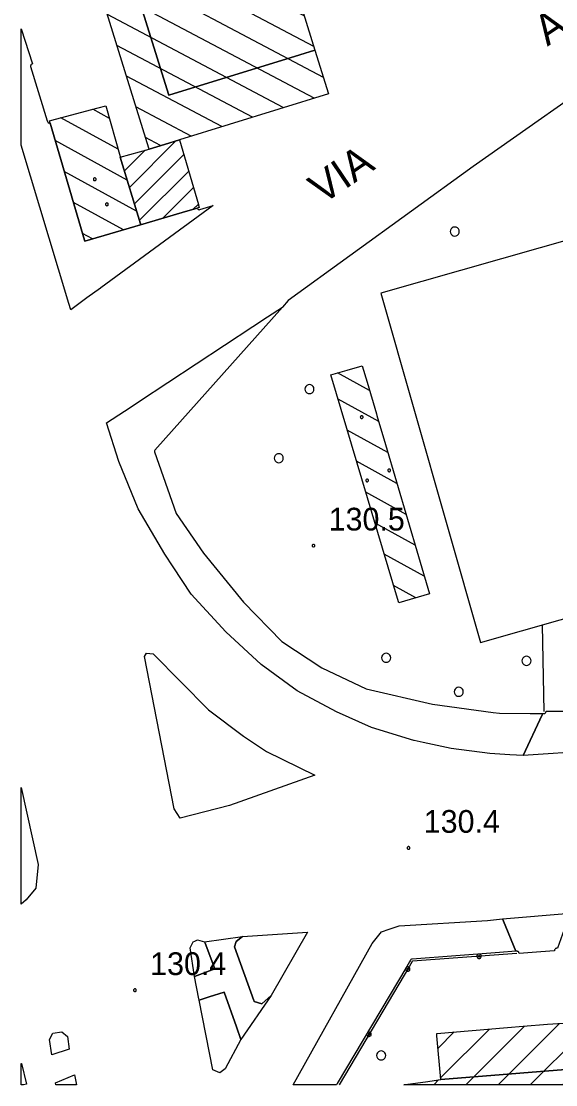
# Model space of a CAD drawing. Extents: x 513373 to 514978, y 5038576 to 5040180.
# Drawn here: x 513373 to 513408.3, y 5038580.1 to 5038650.3 of the extents above; entities that cross this region are included whole.
import ezdxf

# ---------------------------------------------------------------- set-up
doc = ezdxf.new("R2010")
doc.units = 0
for name, color, linetype in [('2010300', 7, 'Continuous'), ('3010204', 7, 'Continuous'), ('3060104', 7, 'Continuous'), ('B1211', 7, 'Continuous'), ('C1131', 7, 'Continuous'), ('C12211', 7, 'Continuous'), ('C21111', 7, 'Continuous'), ('C21152', 7, 'Continuous'), ('C2911', 7, 'Continuous'), ('CAMP_C12211', 7, 'Continuous'), ('CAMP_C21111', 7, 'Continuous'), ('Default', 7, 'Continuous'), ('F12107', 7, 'Continuous'), ('F12131', 7, 'Continuous'), ('F12132', 7, 'Continuous'), ('G4315', 7, 'Continuous'), ('TOP500', 7, 'Continuous'), ('TOP920', 7, 'Continuous')]:
    doc.layers.add(name, color=color, linetype=linetype)

# ---------------------------------------------------------------- blocks, each defined once
blk = doc.blocks.new('CAMP_1CE415D7')
at = {"layer": 'CAMP_C12211'}
for p, q in [((2.937, -2.063), (7.928, 2.928)), ((5.058, -2.063), (10.238, 3.116)), ((7.18, -2.063), (12.549, 3.306)), ((-5.548, -2.063), (-1.311, 2.174)), ((-3.427, -2.063), (0.999, 2.362)), ((-1.306, -2.063), (3.309, 2.551)), ((0.816, -2.063), (5.618, 2.739)), ((-11.619, 0.351), (-10.551, 1.42)), ((-11.442, -1.593), (-8.241, 1.608)), ((-9.791, -2.063), (-5.931, 1.797)), ((-7.669, -2.063), (-3.621, 1.986)), ((9.301, -2.063), (13.227, 1.863)), ((11.422, -2.063), (13.385, -0.1)), ((-11.912, -2.063), (-11.599, -1.75))]:
    blk.add_line(p, q, dxfattribs=at)
blk = doc.blocks.new('CAMP_4260F104')
at = {"layer": 'CAMP_C12211'}
for p, q in [((-0.738, 6.397), (-2.86, 7.563)), ((-0.137, 4.354), (-2.818, 5.829)), ((0.464, 2.312), (-2.208, 3.781)), ((1.065, 0.27), (-1.598, 1.734)), ((1.666, -1.772), (-0.988, -0.313)), ((2.267, -3.814), (-0.378, -2.36)), ((2.868, -5.856), (0.232, -4.407)), ((2.32, -7.267), (0.842, -6.454))]:
    blk.add_line(p, q, dxfattribs=at)
blk = doc.blocks.new('CAMP_4F2082C4')
at = {"layer": 'CAMP_C12211'}
for p, q in [((0.976, 3.743), (-0.129, 4.35)), ((1.54, 1.721), (-2.225, 3.791)), ((2.143, -0.322), (-2.606, 2.288)), ((2.759, -2.373), (-2.004, 0.246)), ((1.887, -3.605), (-1.402, -1.797)), ((-0.139, -4.203), (-0.8, -3.839))]:
    blk.add_line(p, q, dxfattribs=at)
blk = doc.blocks.new('CAMP_3A5802B0')
at = {"layer": 'CAMP_C12211'}
for p, q in [((-2.527, 26.797), (-4.04, 27.598)), ((-1.899, 24.767), (-6.054, 26.968)), ((-1.271, 22.738), (-7.369, 25.967)), ((-0.644, 20.708), (-7.369, 24.269)), ((-0.016, 18.679), (-7.369, 22.572)), ((0.612, 16.649), (-7.369, 20.875)), ((1.24, 14.619), (-7.369, 19.177)), ((1.867, 12.59), (-7.369, 17.48)), ((2.495, 10.56), (-7.369, 15.783)), ((3.123, 8.53), (-7.369, 14.086)), ((3.75, 6.501), (-7.369, 12.388)), ((4.378, 4.471), (-7.369, 10.691)), ((5.006, 2.441), (-7.369, 8.994)), ((5.634, 0.412), (-7.37, 7.297)), ((6.261, -1.618), (-7.37, 5.599)), ((6.889, -3.648), (-7.37, 3.902)), ((7.517, -5.677), (-7.37, 2.205)), ((8.144, -7.707), (-7.345, 0.494)), ((8.772, -9.736), (-6.717, -1.535)), ((9.4, -11.766), (-6.089, -3.565)), ((10.028, -13.796), (-5.461, -5.595)), ((10.655, -15.825), (-4.833, -7.625)), ((11.283, -17.855), (-4.206, -9.654)), ((11.911, -19.885), (-3.578, -11.684)), ((12.539, -21.914), (-2.95, -13.714)), ((11.923, -23.286), (-2.322, -15.743)), ((9.9, -23.912), (-1.695, -17.773)), ((7.876, -24.538), (-1.067, -19.803)), ((5.853, -25.164), (-0.439, -21.832)), ((3.829, -25.79), (0.188, -23.862)), ((1.806, -26.415), (0.816, -25.891))]:
    blk.add_line(p, q, dxfattribs=at)
blk = doc.blocks.new('CAMP_029225B5')
at = {"layer": 'CAMP_C21111'}
for p, q in [((-2.285, -0.164), (0.782, 2.904)), ((-2.612, 0.924), (-1.253, 2.283)), ((-1.959, -1.251), (1.301, 2.008)), ((-1.632, -2.339), (1.62, 0.912)), ((-0.079, -2.201), (1.938, -0.183)), ((1.921, -1.614), (2.257, -1.278))]:
    blk.add_line(p, q, dxfattribs=at)
blk = doc.blocks.new('03080200')
at = {"layer": 'Default'}
for p, q in [((-0.139, 0.046), (-0.146, 0)), ((-0.146, 0), (-0.139, -0.046)), ((-0.118, 0.086), (-0.139, 0.046)), ((-0.086, 0.118), (-0.118, 0.086)), ((-0.046, 0.139), (-0.086, 0.118)), ((0, 0.146), (-0.046, 0.139)), ((-0.042, 0.014), (-0.045, 0)), ((-0.045, 0), (-0.042, -0.014)), ((-0.036, 0.026), (-0.042, 0.014)), ((-0.026, 0.036), (-0.036, 0.026)), ((-0.014, 0.042), (-0.026, 0.036)), ((0, 0.045), (-0.014, 0.042)), ((0.046, 0.139), (0, 0.146)), ((0.014, 0.042), (0, 0.045)), ((0.026, 0.036), (0.014, 0.042)), ((0.036, 0.026), (0.026, 0.036)), ((0.042, 0.014), (0.036, 0.026)), ((0.045, 0), (0.042, 0.014)), ((0.042, -0.014), (0.045, 0)), ((0.086, 0.118), (0.046, 0.139)), ((0.118, 0.086), (0.086, 0.118)), ((0.139, 0.046), (0.118, 0.086)), ((0.146, 0), (0.139, 0.046)), ((0.139, -0.046), (0.146, 0)), ((-0.139, -0.046), (-0.118, -0.086)), ((-0.118, -0.086), (-0.086, -0.118)), ((-0.086, -0.118), (-0.046, -0.139)), ((-0.046, -0.139), (0, -0.146)), ((-0.042, -0.014), (-0.036, -0.026)), ((-0.036, -0.026), (-0.026, -0.036)), ((-0.026, -0.036), (-0.014, -0.042)), ((-0.014, -0.042), (0, -0.045)), ((0, -0.045), (0.014, -0.042)), ((0, -0.146), (0.046, -0.139)), ((0.014, -0.042), (0.026, -0.036)), ((0.026, -0.036), (0.036, -0.026)), ((0.036, -0.026), (0.042, -0.014)), ((0.046, -0.139), (0.086, -0.118)), ((0.086, -0.118), (0.118, -0.086)), ((0.118, -0.086), (0.139, -0.046))]:
    blk.add_line(p, q, dxfattribs=at)
blk = doc.blocks.new('08020400')
at = {"layer": 'Default'}
for p, q in [((-0.086, 0.028), (-0.09, 0)), ((-0.09, 0), (-0.086, -0.028)), ((-0.073, 0.053), (-0.086, 0.028)), ((-0.053, 0.073), (-0.073, 0.053)), ((-0.028, 0.086), (-0.053, 0.073)), ((0, 0.09), (-0.028, 0.086)), ((0.028, 0.086), (0, 0.09)), ((0.053, 0.073), (0.028, 0.086)), ((0.073, 0.053), (0.053, 0.073)), ((0.086, 0.028), (0.073, 0.053)), ((0.09, 0), (0.086, 0.028)), ((0.086, -0.028), (0.09, 0)), ((-0.086, -0.028), (-0.073, -0.053)), ((-0.073, -0.053), (-0.053, -0.073)), ((-0.053, -0.073), (-0.028, -0.086)), ((-0.028, -0.086), (0, -0.09)), ((0, -0.09), (0.028, -0.086)), ((0.028, -0.086), (0.053, -0.073)), ((0.053, -0.073), (0.073, -0.053)), ((0.073, -0.053), (0.086, -0.028))]:
    blk.add_line(p, q, dxfattribs=at)
blk = doc.blocks.new('NSIMB25')
at = {"layer": 'Default'}
for p, q in [((-0.086, 0.028), (-0.09, 0)), ((-0.09, 0), (-0.086, -0.028)), ((-0.073, 0.053), (-0.086, 0.028)), ((-0.053, 0.073), (-0.073, 0.053)), ((-0.028, 0.086), (-0.053, 0.073)), ((0, 0.09), (-0.028, 0.086)), ((0.028, 0.086), (0, 0.09)), ((0.053, 0.073), (0.028, 0.086)), ((0.073, 0.053), (0.053, 0.073)), ((0.086, 0.028), (0.073, 0.053)), ((0.09, 0), (0.086, 0.028)), ((0.086, -0.028), (0.09, 0)), ((-0.086, -0.028), (-0.073, -0.053)), ((-0.073, -0.053), (-0.053, -0.073)), ((-0.053, -0.073), (-0.028, -0.086)), ((-0.028, -0.086), (0, -0.09)), ((0, -0.09), (0.028, -0.086)), ((0.028, -0.086), (0.053, -0.073)), ((0.053, -0.073), (0.073, -0.053)), ((0.073, -0.053), (0.086, -0.028))]:
    blk.add_line(p, q, dxfattribs=at)
blk = doc.blocks.new('05010100')
at = {"layer": 'Default'}
for p, q in [((-0.143, 0.046), (-0.15, 0)), ((-0.15, 0), (-0.143, -0.046)), ((-0.121, 0.088), (-0.143, 0.046)), ((-0.088, 0.121), (-0.121, 0.088)), ((-0.046, 0.143), (-0.088, 0.121)), ((0, 0.15), (-0.046, 0.143)), ((0.046, 0.143), (0, 0.15)), ((0.088, 0.121), (0.046, 0.143)), ((0.121, 0.088), (0.088, 0.121)), ((0.143, 0.046), (0.121, 0.088)), ((0.15, 0), (0.143, 0.046)), ((0.143, -0.046), (0.15, 0)), ((-0.143, -0.046), (-0.121, -0.088)), ((-0.121, -0.088), (-0.088, -0.121)), ((-0.088, -0.121), (-0.046, -0.143)), ((-0.046, -0.143), (0, -0.15)), ((0, -0.15), (0.046, -0.143)), ((0.046, -0.143), (0.088, -0.121)), ((0.088, -0.121), (0.121, -0.088)), ((0.121, -0.088), (0.143, -0.046))]:
    blk.add_line(p, q, dxfattribs=at)
blk = doc.blocks.new('A$C3704598A')
at = {"layer": '2010300'}
for points in [[(63.875, -708.514), (65.701, -714.881), (66.154, -716.461), (50.099, -726.135), (45.283, -729.066), (39.595, -732.528), (29.764, -739.427), (17.578, -748.279), (17.196, -748.707), (8.795, -758.134), (8.774, -758.179), (8.768, -758.22), (8.774, -758.259)], [(-0.009, -730.353), (0.73, -732.661), (0.675, -732.68), (0.648, -732.701), (0.627, -732.728), (0.612, -732.764), (0.61, -732.77), (0.604, -732.797), (0.608, -732.833), (1.699, -736.423), (1.714, -736.473), (1.738, -736.515), (1.769, -736.542), (1.811, -736.562), (1.852, -736.568), (1.885, -736.564)], [(8.774, -758.259), (10.194, -762.323), (11.989, -764.94), (14.629, -768.172), (17.166, -770.769), (19.793, -772.501), (22.724, -773.891), (27.093, -774.907), (31.098, -775.444), (31.509, -775.5)], [(31.509, -775.5), (33.519, -775.514), (34.359, -775.521), (34.445, -775.519), (34.49, -775.507), (34.525, -775.485), (34.556, -775.448), (34.572, -775.409), (34.576, -775.359)], [(35.14, -791.17), (34.228, -791.241), (32.804, -791.349)]]:
    blk.add_lwpolyline(points, dxfattribs=at)
at = {"layer": '3010204'}
blk.add_lwpolyline([(34.331, -769.676), (34.429, -775.371)], dxfattribs=at)
at = {"layer": '3060104'}
blk.add_lwpolyline([(23.688, -747.789), (30.258, -770.837), (43.469, -767.071), (36.899, -744.023), (23.688, -747.789)], dxfattribs=at)
at = {"layer": 'B1211'}
for points in [[(-0.009, -730.353), (0.73, -732.661), (0.675, -732.68), (0.648, -732.701), (0.627, -732.728), (0.612, -732.764), (0.61, -732.77), (0.604, -732.797), (0.608, -732.833), (1.699, -736.423), (1.714, -736.473), (1.738, -736.515), (1.769, -736.542), (1.811, -736.562), (1.852, -736.568), (1.885, -736.564), (4.165, -744.302), (4.181, -744.358), (7.858, -743.273), (10.592, -742.471), (11.581, -742.181), (11.595, -742.212), (11.624, -742.245), (11.632, -742.251), (11.648, -742.262), (11.679, -742.276), (11.718, -742.282), (11.753, -742.279), (12.64, -742.014), (5.233, -747.437), (5.206, -747.458), (4.321, -748.106), (3.255, -748.886), (3.131, -748.47), (2.449, -746.204), (-0.009, -738.021), (-0.01, -730.352)], [(34.323, -775.598), (33.075, -778.291), (32.19, -778.238), (30.867, -778.159), (28.328, -777.832), (26.784, -777.491), (26.487, -777.425), (25.889, -777.293), (25.861, -777.285), (23.074, -776.437), (20.762, -775.4), (18.17, -774.025), (15.798, -772.274), (13.48, -770.119), (11.192, -767.633), (9.999, -765.835), (9.453, -765.012), (7.696, -762.011), (6.417, -758.899), (5.603, -756.342), (6.784, -755.564), (7.687, -754.969), (7.785, -754.905), (15.244, -749.992), (16.212, -749.355), (17.196, -748.707), (8.795, -758.134), (8.774, -758.179), (8.768, -758.22), (8.774, -758.259), (10.194, -762.323), (11.989, -764.94), (14.629, -768.172), (17.166, -770.769), (19.793, -772.501), (22.724, -773.891), (27.093, -774.907), (31.098, -775.444), (31.509, -775.5), (33.519, -775.514), (34.359, -775.521)], [(36.874, -775.359), (36.871, -775.404), (36.88, -775.442), (36.895, -775.472), (36.907, -775.486), (36.914, -775.495), (36.941, -775.516), (36.972, -775.531), (37.005, -775.537), (37.076, -775.539), (37.169, -775.785), (37.775, -777.377), (39.03, -777.882), (37.652, -777.977), (33.075, -778.291), (34.323, -775.598), (34.359, -775.521), (34.445, -775.519), (34.49, -775.507), (34.525, -775.485), (34.556, -775.448), (34.572, -775.409), (34.576, -775.359), (35.967, -775.359)], [(1.097, -785.479), (0.942, -787.029), (0.322, -787.804), (-0.01, -788.087), (-0.01, -780.385)], [(31.771, -789.207), (32.594, -791.198), (31.51, -791.279), (25.745, -791.712), (25.706, -791.723), (25.674, -791.742), (25.643, -791.775), (25.577, -791.886), (25.39, -792.202), (20.809, -799.929), (20.767, -800), (17.904, -800), (23.108, -790.692), (23.728, -789.917), (24.246, -789.744), (24.891, -789.529), (30.723, -789.157), (31.711, -789.061)], [(35.341, -790.991), (35.266, -790.997), (35.233, -791.006), (35.199, -791.024), (35.167, -791.055), (35.152, -791.08), (35.141, -791.112), (35.14, -791.17), (34.228, -791.241), (32.804, -791.349), (32.793, -791.289), (32.773, -791.253), (32.74, -791.221), (32.703, -791.202), (32.662, -791.195), (32.594, -791.198), (31.771, -789.207), (31.711, -789.061), (36.159, -788.677), (36.103, -788.834)], [(16.452, -794.119), (14.47, -797.012), (14.178, -796.189), (13.365, -793.892), (12.371, -794.203), (11.707, -794.412), (11.692, -794.336), (11.415, -792.852), (12.747, -792.364), (12.099, -790.665), (12.065, -790.577), (14.567, -790.219), (14.145, -790.544), (14.047, -790.902), (15.327, -794.453), (15.341, -794.492), (15.347, -794.509), (15.835, -794.672)]]:
    blk.add_lwpolyline(points, close=True, dxfattribs=at)
at = {"layer": 'C1131'}
for points in [[(19.345, -731.764), (18.346, -732.072), (9.716, -734.736), (9.695, -734.668), (-0.009, -703.475), (-0.009, -688.08), (4.323, -686.733), (5.322, -686.422)], [(9.695, -734.668), (9.716, -734.736), (18.346, -732.072), (19.345, -731.764), (20.232, -734.631), (10.421, -737.666), (9.422, -737.975), (8.41, -738.288), (8.389, -738.219), (6.222, -731.209), (-0.009, -711.064), (-0.009, -703.475)], [(6.518, -738.813), (7.842, -743.219), (7.858, -743.273), (4.181, -744.358), (4.165, -744.302), (1.885, -736.564), (1.852, -736.418), (1.995, -736.376), (4.56, -735.692), (5.572, -735.422), (6.507, -738.773)], [(11.68, -741.989), (11.722, -742.133), (11.581, -742.181), (10.592, -742.471), (7.858, -743.273), (7.842, -743.219), (6.518, -738.813), (8.41, -738.288), (9.422, -737.975), (10.421, -737.666), (11.662, -741.929)], [(26.891, -767.611), (24.869, -768.207), (24.852, -768.151), (20.387, -753.167), (21.461, -752.862), (22.467, -752.577), (22.783, -753.651), (23.398, -755.742), (23.434, -755.861), (23.995, -757.771)], [(49.495, -797.911), (48.464, -797.994), (27.652, -799.664), (27.389, -796.766), (27.375, -796.612), (32.034, -796.231), (33.066, -796.147), (34.67, -796.016), (35.704, -795.932), (49.277, -794.824), (49.287, -794.978)], [(49.671, -800), (25.469, -800), (25.463, -799.965), (26.624, -799.805), (27.652, -799.664), (48.464, -797.994), (49.495, -797.911)], [(25.469, -800), (25.207, -800), (25.463, -799.965)]]:
    blk.add_lwpolyline(points, close=True, dxfattribs=at)
at = {"layer": 'C12211'}
for points in [[(4.503, -683.775), (4.521, -683.833), (5.322, -686.422), (19.345, -731.764), (20.232, -734.631), (10.421, -737.666), (9.422, -737.975), (8.41, -738.288), (8.389, -738.219), (6.222, -731.209), (-0.009, -711.064), (-0.009, -685.083), (3.475, -683.992), (4.332, -683.724), (4.477, -683.691)], [(6.518, -738.813), (7.842, -743.219), (7.858, -743.273), (4.181, -744.358), (4.165, -744.302), (1.885, -736.564), (1.852, -736.418), (1.995, -736.376), (4.56, -735.692), (5.572, -735.422), (6.507, -738.773)], [(26.891, -767.611), (24.869, -768.207), (24.852, -768.151), (20.387, -753.167), (21.461, -752.862), (22.467, -752.577), (22.783, -753.651), (23.398, -755.742), (23.434, -755.861), (23.995, -757.771)], [(52.201, -794.733), (52.625, -800), (25.207, -800), (25.463, -799.965), (26.624, -799.805), (27.652, -799.664), (27.389, -796.766), (27.375, -796.612), (32.034, -796.231), (33.066, -796.147), (34.67, -796.016), (35.704, -795.932), (49.277, -794.824), (50.991, -794.684), (51.291, -794.659), (52.022, -794.599), (52.172, -794.586)]]:
    blk.add_lwpolyline(points, close=True, dxfattribs=at)
at = {"layer": 'C21111'}
blk.add_lwpolyline([(11.68, -741.989), (11.722, -742.133), (11.581, -742.181), (10.592, -742.471), (7.858, -743.273), (7.842, -743.219), (6.518, -738.813), (8.41, -738.288), (9.422, -737.975), (10.421, -737.666), (11.662, -741.929)], close=True, dxfattribs=at)
at = {"layer": 'C21152'}
for points in [[(19.333, -779.582), (13.721, -781.583), (10.459, -782.409), (10.067, -781.8), (8.11, -771.752), (8.24, -771.534), (8.675, -771.578), (12.329, -775.275), (14.635, -777.015), (16.157, -778.016)], [(12.747, -792.364), (11.415, -792.852), (11.122, -790.967), (11.252, -790.707), (11.317, -790.577), (11.434, -790.525), (11.61, -790.447), (12.065, -790.577), (12.099, -790.665)], [(16.452, -794.119), (15.835, -794.672), (15.347, -794.509), (15.341, -794.492), (15.327, -794.453), (14.047, -790.902), (14.145, -790.544), (14.567, -790.219), (18.857, -789.927)], [(14.47, -797.012), (13.43, -798.962), (13.072, -799.222), (12.617, -799.027), (11.707, -794.412), (12.371, -794.203), (13.365, -793.892), (14.178, -796.189)], [(1.846, -797.009), (2.078, -796.606), (2.666, -796.508), (3.034, -796.826), (3.156, -797.659), (2.008, -798.017)], [(0.339, -799.962), (0.126, -800), (-0.01, -800), (-0.01, -798.593), (-0.004, -798.59)], [(3.619, -800), (2.271, -800), (2.245, -799.877), (3.507, -799.355)]]:
    blk.add_lwpolyline(points, close=True, dxfattribs=at)
at = {"layer": 'C2911'}
blk.add_lwpolyline([(32.655, -791.343), (25.766, -791.86), (25.758, -791.873), (25.571, -792.188), (20.94, -800)], dxfattribs=at)
for p, rotation in [((30.162, -791.53), -175.70904568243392), ((25.464, -792.369), -120.66331028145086), ((22.914, -796.67), -120.66331028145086)]:
    blk.add_blockref('03080200', p, dxfattribs=dict(at, rotation=rotation))
at = {"layer": 'CAMP_C12211'}
for name, p in [('CAMP_3A5802B0', (7.36, -711.639)), ('CAMP_4F2082C4', (4.83, -740.004)), ('CAMP_4260F104', (23.685, -760.606)), ('CAMP_1CE415D7', (39.082, -797.937))]:
    blk.add_blockref(name, p, dxfattribs=at)
at = {"layer": 'CAMP_C21111'}
blk.add_blockref('CAMP_029225B5', (9.403, -740.643), dxfattribs=at)
at = {"layer": 'F12107'}
for p in [(19.248, -764.443), (25.514, -784.382), (7.482, -793.766)]:
    blk.add_blockref('08020400', p, dxfattribs=at)
at = {"layer": 'F12131'}
for p in [(5.636, -741.928), (22.426, -755.963)]:
    blk.add_blockref('NSIMB25', p, dxfattribs=at)
at = {"layer": 'F12132'}
for p in [(4.833, -740.275), (24.24, -759.478), (22.783, -760.142)]:
    blk.add_blockref('NSIMB25', p, dxfattribs=at)
at = {"layer": 'G4315', "xscale": 2, "yscale": 2}
for p in [(28.556, -743.723), (18.982, -754.111), (16.958, -758.675), (24.042, -771.831), (33.289, -772.039), (28.819, -774.074), (23.712, -798.062)]:
    blk.add_blockref('05010100', p, dxfattribs=at)
at = {"layer": 'TOP500'}
for s, p in [('A.', (34.665, -731.532)), ('VIA', (19.83, -741.97))]:
    blk.add_text(s, height=2, rotation=34.05122, dxfattribs=at).set_placement(p)
at = {"layer": 'TOP920'}
for s, p in [('130.5', (20.248, -763.443)), ('130.4', (26.514, -783.382)), ('130.4', (8.482, -792.766))]:
    blk.add_text(s, height=1.5, dxfattribs=at).set_placement(p)

msp = doc.modelspace()

# ---------------------------------------------------------------- block references
at = {"layer": 'Default'}
msp.add_blockref('A$C3704598A', (513373.046, 5039380.14), dxfattribs=at)

doc.saveas('drawing.dxf')
